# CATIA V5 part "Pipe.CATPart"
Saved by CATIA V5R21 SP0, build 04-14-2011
Part number: Pipe
Bounding box of the stored display mesh (mm): x -50 to 50, y 0 to 150, z -50 to 50
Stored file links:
  D:\CATIA V5R21 E-RESOURCES\CATIA-V5R21\catia-v5r21-Prts\c12_catia_v5r21_prt\c12_catia_v5r21figr_12-44\Pipe.CATPart
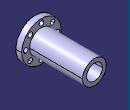
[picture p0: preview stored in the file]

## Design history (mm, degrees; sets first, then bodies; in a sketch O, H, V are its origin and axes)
Body1 (main body)
  Sketch1 on zx-plane, origin (0, 0, 0), H (-1, 0, 0), V (0, 0, 1)
    circle A1 centre (0, 0) radius 50
    point P1 (0, -50)
    circle A2 centre (0, 0) radius 30
    point P2 (0, -30)
    radius A1 = 50
    radius A2 = 30
    coincidence: A1 P1, P1 V, A2 P2, P2 V
  MultiPad1: profile Sketch1, domains (length 150; length 15)
  Sketch2 on face of MultiPad1, origin (0, 150, 0), H (-1, 0, 0), V (0, 0, 1)
    circle A1 centre (0, 0) radius 20
    point P1 (0, -20)
    radius A1 = 20
    coincidence: A1 P1, P1 V
  Pocket1: profile Sketch2, direction (0, -1, 0), through (limit type 3)
  Sketch3 on face of MultiPad1, origin (0, 0, 0), H (1, 0, 0), V (0, 0, 1)
    circle A1 centre (0, -40) radius 6
    point P1 (0, -40)
    radius A1 = 6
    distance H P1 = 40
    coincidence: P1 V
  Pocket2: profile Sketch3, direction (0, 1, 0), through (limit type 3)
  CircPattern1: of Pocket2, instances 8, angular step 45, axis from face of MultiPad1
